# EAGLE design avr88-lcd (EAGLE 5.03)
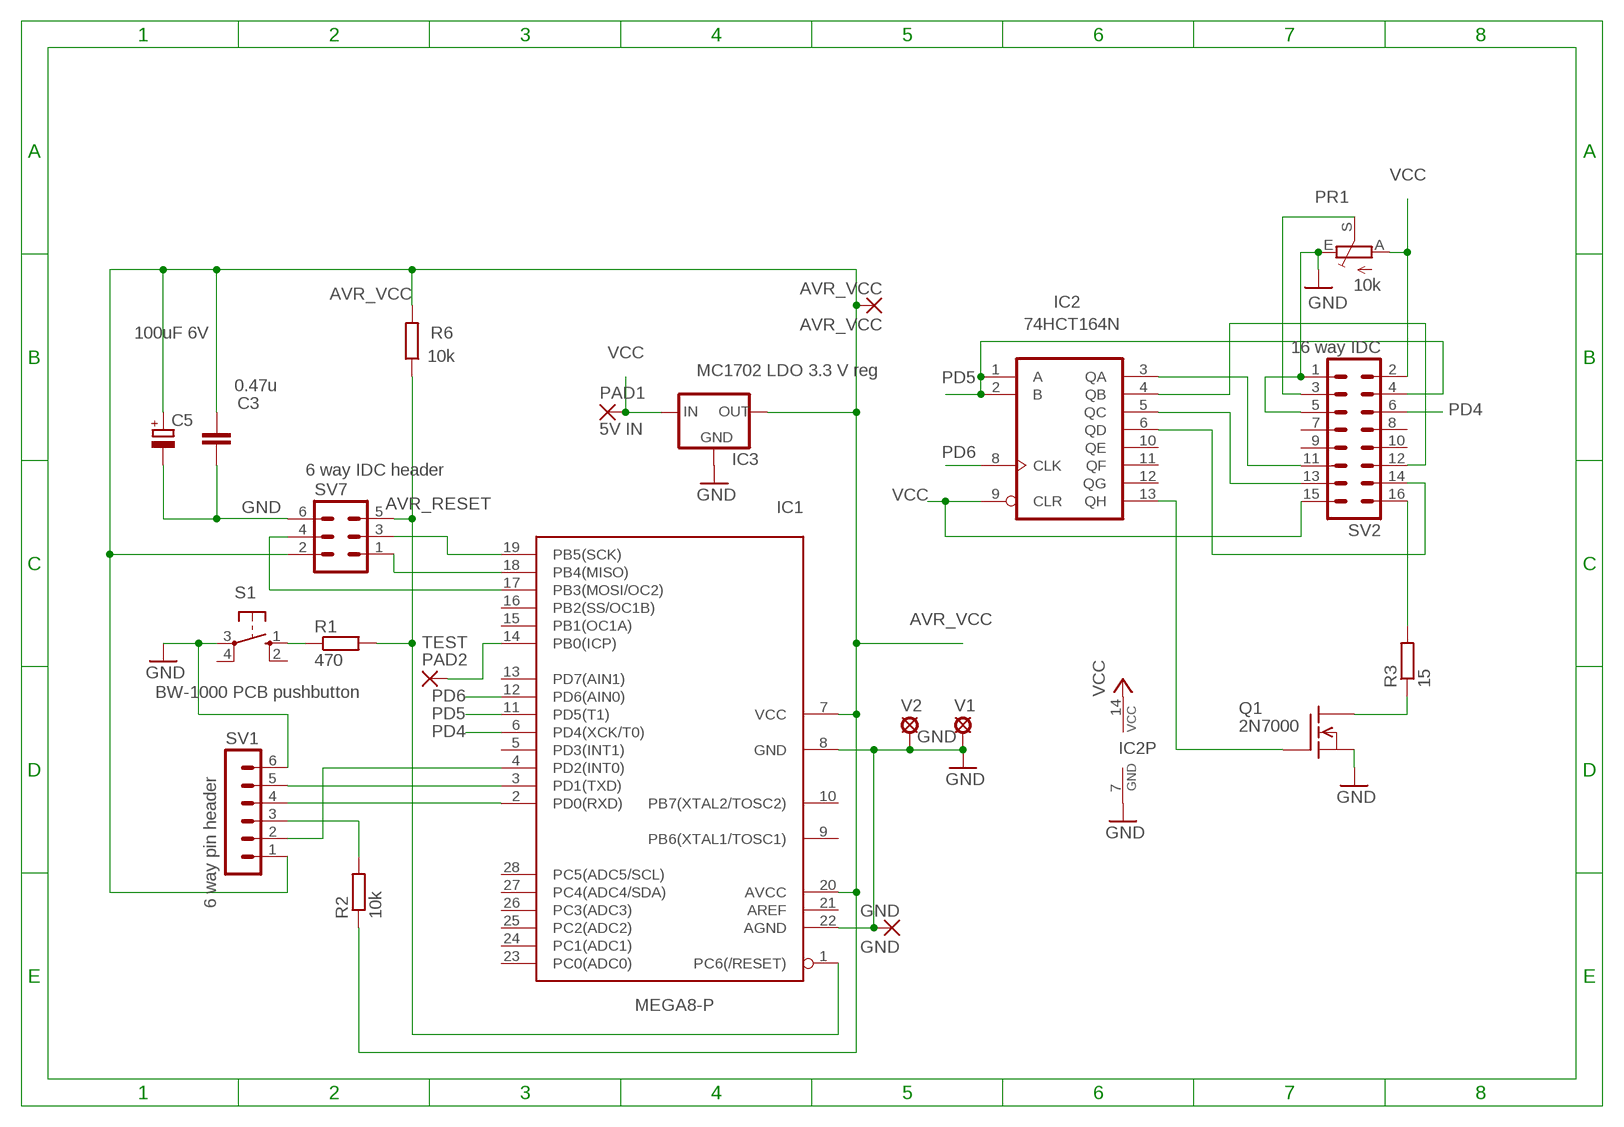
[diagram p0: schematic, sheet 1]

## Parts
AVR_VCC  AVR_VCC  PAD-TERMINAL  [2,54/1,1]
C3  0.47u  C5P  [C050-030-075]
C5  100uF 6V  CPOL1  [E2,5-7---100UF]
GND  GND  PAD-TERMINAL  [2,54/1,1]
IC1  MEGA8-P  [DIL28-3]
IC2  74HCT164N  [DIL14]
IC3  MC1702 LDO 3.3 V reg  XC63FPT  [TO92]
PAD1  5V IN  PAD-TERMINAL  [2,54/1,1]
PAD2  TEST  PAD-TERMINAL  [2,54/1,1]
PR1  10k  VAR_RESISTOR_TRIMS63P  [S63P]
Q1  2N7000  [TO92]
R1  470  R  [0207/10]
R2  10k  R  [0207/10]
R3  15  R  [0207/10]
R6  10k  R  [0207/10]
S1  BW-1000 PCB pushbutton  10-XX  [B3F-10XX]
SV1  6 way pin header  MA06-1  [MA06-1]
SV2  16 way IDC  ML16L  [ML16L]
SV7  6 way IDC header  ML6  [ML6]
V1  HOLE-VIA  [LSP10]
V2  HOLE-VIA  [LSP10]

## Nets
AVR_RESET: IC1.1(PC6(/RESET)) R1.2 R6.1 SV7.5
AVR_VCC: AVR_VCC.1(P) C3.2 C5.+ IC1.7(VCC) IC1.20(AVCC) IC3.3(OUT) R2.1 R6.2 SV1.1 SV7.2
GND [supply]: C3.1 C5.- GND.1(P) IC1.8(GND) IC1.22(AGND) IC2.7(GND) IC3.1(GND) PR1.E Q1.3(S) S1.3(P) SV1.6 SV2.1 SV2.5 SV7.6 V1.MP V2.MP
N$1: Q1.1(D) R3.1
N$2: IC1.19(PB5(SCK)) SV7.3
N$3: IC1.18(PB4(MISO)) SV7.1
N$4: IC1.3(PD1(TXD)) SV1.5
N$5: IC1.2(PD0(RXD)) SV1.4
N$6: IC1.4(PD2(INT0)) SV1.2
N$7: R2.2 SV1.3
N$8: IC1.17(PB3(MOSI/OC2)) SV7.4
N$9: IC2.13(QH) Q1.2(G)
N$10: IC1.14(PB0(ICP)) PAD2.1(P)
N$13: IC2.6(QD) SV2.14
N$14: IC2.5(QC) SV2.13
N$15: IC2.4(QB) SV2.12
N$16: IC2.3(QA) SV2.11
N$17 [supply]: R1.1 S1.1(S)
N$18: PR1.S SV2.3
N$19: R3.2 SV2.16
PD4: IC1.6(PD4(XCK/T0)) SV2.6
PD5: IC1.11(PD5(T1)) IC2.1(A) IC2.2(B) SV2.4
PD6: IC1.12(PD6(AIN0)) IC2.8(CLK)
VCC [supply]: IC2.9(CLR) IC2.14(VCC) IC3.2(IN) PAD1.1(P) PR1.A SV2.2 SV2.15
Unconnected: IC1.5(PD3(INT1)) IC1.9(PB6(XTAL1/TOSC1)) IC1.10(PB7(XTAL2/TOSC2)) IC1.13(PD7(AIN1)) IC1.15(PB1(OC1A)) IC1.16(PB2(SS/OC1B)) IC1.21(AREF) IC1.23(PC0(ADC0)) IC1.24(PC1(ADC1)) IC1.25(PC2(ADC2)) IC1.26(PC3(ADC3)) IC1.27(PC4(ADC4/SDA)) IC1.28(PC5(ADC5/SCL)) IC2.10(QE) IC2.11(QF) IC2.12(QG) S1.2(S1) S1.4(P1) SV2.7 SV2.8 SV2.9 SV2.10

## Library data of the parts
AVR_VCC GND PAD1 PAD2 = ee2parts:PAD-TERMINAL: LARGE THROUGH-HOLE PAD
C3 = ee2parts:C: Capacitor
C5 = ee2parts:CPOL: Electrolytic (polarised) capacitor
IC1 = atmel:MEGA8-P: MICROCONTROLLER 8 Kbytes FLASH, 1 kbytes SRAM, 512 bytes EEPROM, USART, 4-channel 10 bit ADC, 2-channel 8 bit ADC Pin compatible with Atmega48, ATMega88, ATMega168 Source: avr.lbr
IC2 = 74xx-eu:74*164: 8-bit parallel out SHIFT REGISTER
IC3 = v-reg:XC63FP: Positiv Voltage Regulators www.torex.co.jp/english/product/pro02/pdf/0201_xc62fp.pdf
PR1 = ee2parts:VAR_RESISTOR_TRIM: Variable resistor / potentiometer Trimmer potentiometer - Note that slider to end makes variable resistance
Q1 = z-avr-lcd-noPTH:2N7000: N-Channel Enhancement MOSFET 200V; 0,16A; 11Ohm
R1-R3 R6 = ee2parts:R: Resistor
S1 = switch-omron:10-XX: OMRON SWITCH
SV1 = con-lstb:MA06-1: PIN HEADER
SV2 = con-harting-ml:ML16: HARTING
SV7 = con-harting-ml:ML6: HARTING
V1 = ee2parts:HOLE-VIA: FIXED VIA
V2 = z-avr-lcd-noPTH:HOLE-VIA: FIXED VIA

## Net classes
1 supply: width 0.635 mm

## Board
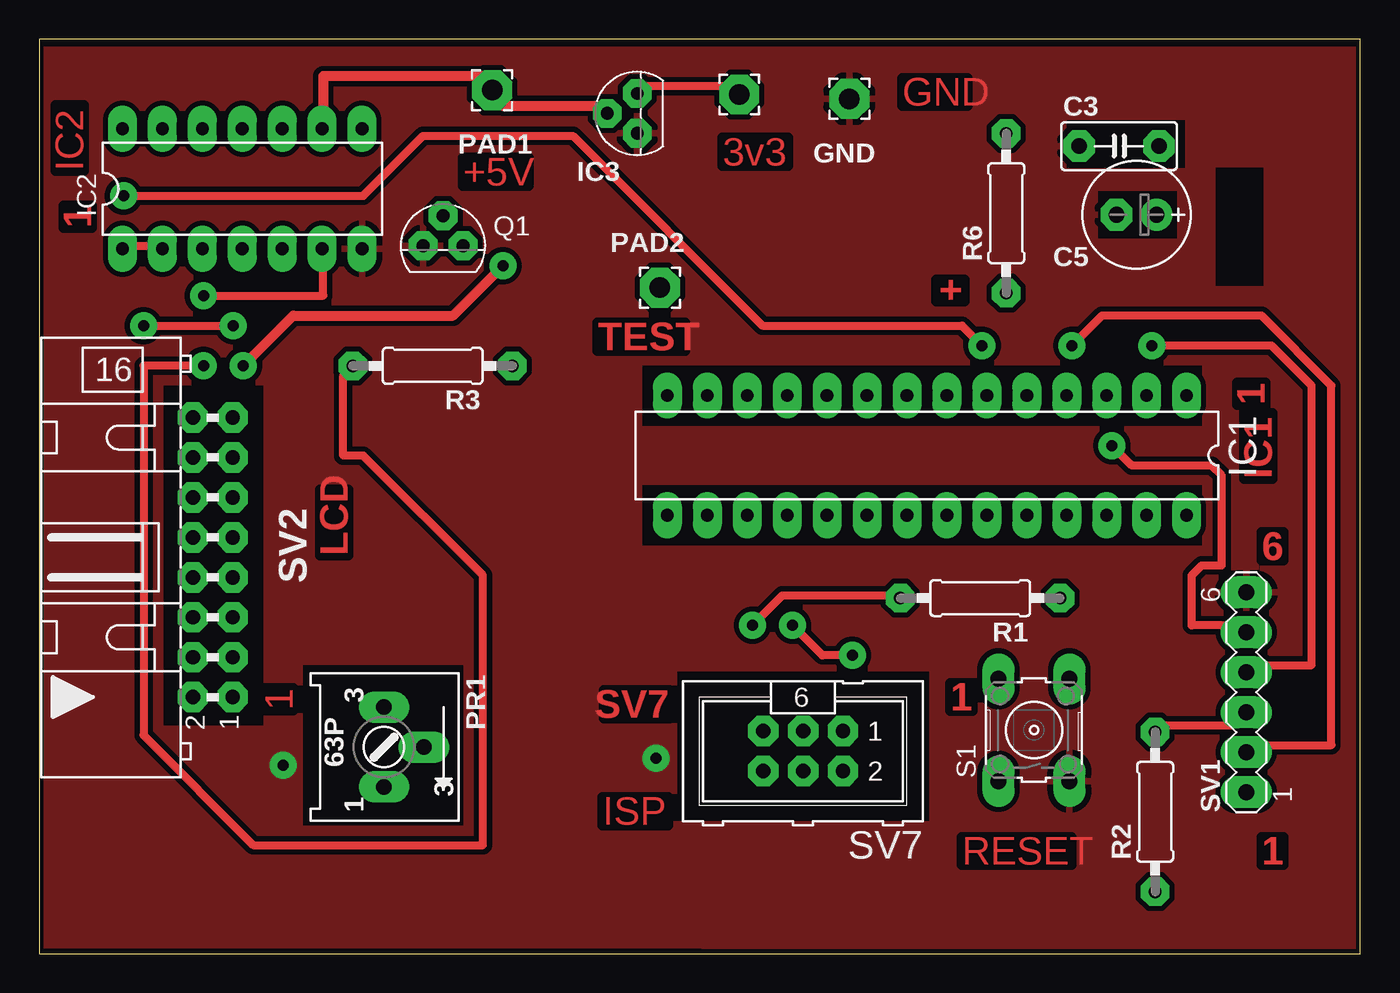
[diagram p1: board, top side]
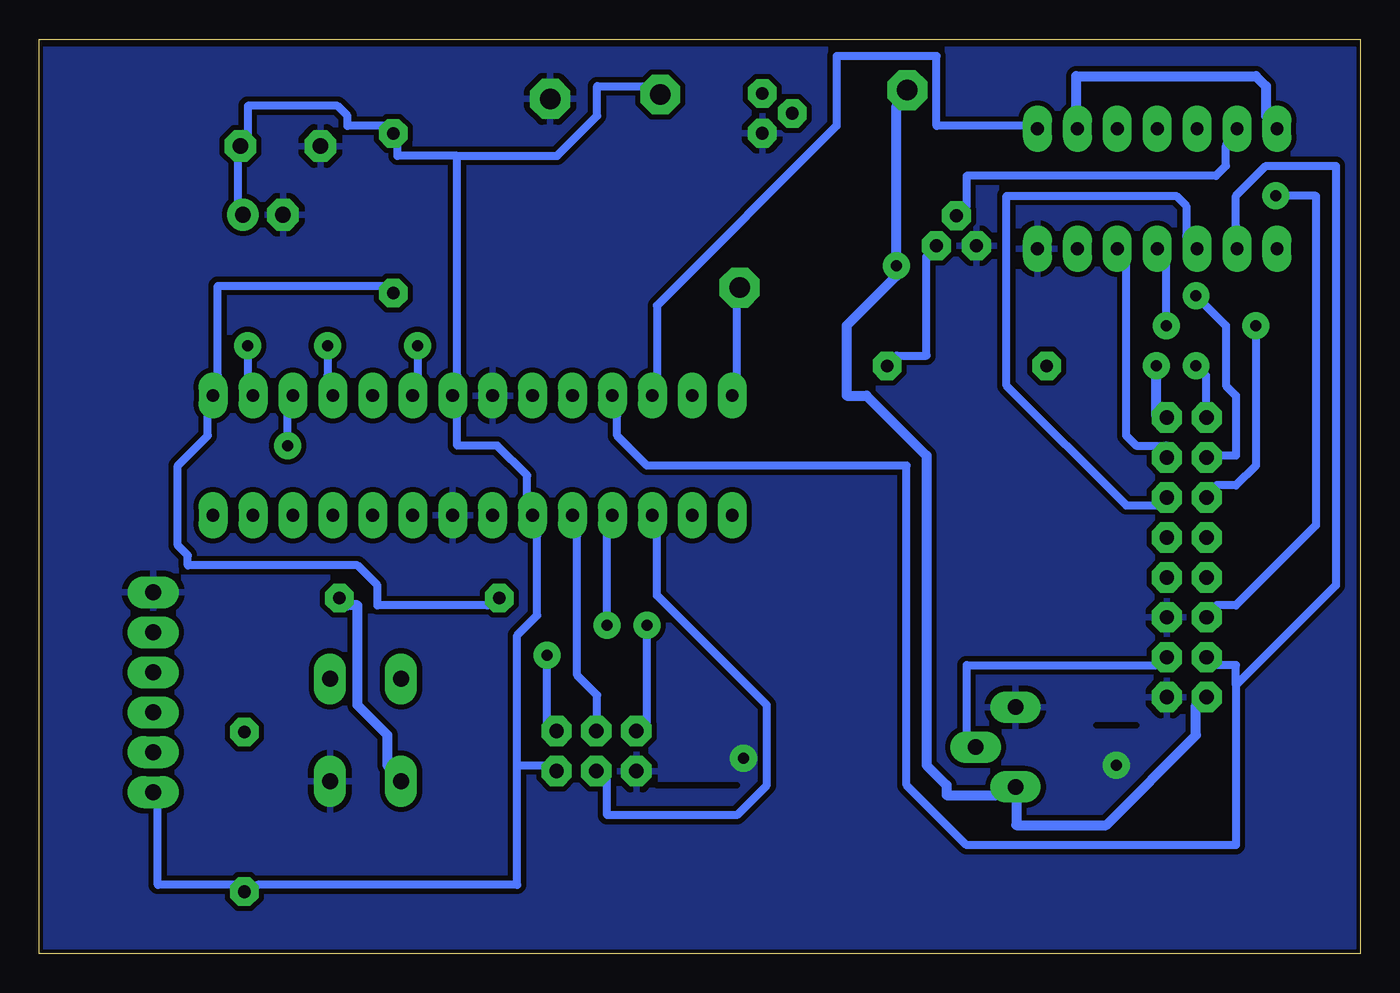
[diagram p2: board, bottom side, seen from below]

Size 84.02 x 58.13 mm. Coordinates in mm from the lower left corner, seen from the top.
Outline: 84.02,0 84.02,58.13 0,58.13 0,0 84.02,0
Copper layers (1*16): Top 0.035mm / dielectric 1.5mm / Bottom 0.035mm
Design rules "zigbit_rules *": minimum track width 20mil, minimum drill 0.7mm, track to track 13mil, track to pad 13mil, pad to pad 13mil, via to via 13mil, smd to smd 0mil, copper to edge 10mil, drill to drill 10mil, minimum pad ring 20mil, minimum via ring 20mil, stop-mask expansion 0mil, vias tented up to drill 0mil, thermal gap 15mil
tRestrict: area 67.3,45.5 to 72.3,48.5; area 65.3,50 to 72.8,53; area 74.8,42.5 to 77.8,50; area 40.6,8.4 to 56.6,17.9; area 7.9,14.5 to 14.3,36.1; area 16.8,8.2 to 27,18.3; area 38.4,33.6 to 73.9,37.4; area 38.4,25.9 to 73.9,29.8
bRestrict: 2 lines
vRestrict: area 0.3,10.7 to 9.2,38.6; area 14.2,14.5 to 19.3,36.1

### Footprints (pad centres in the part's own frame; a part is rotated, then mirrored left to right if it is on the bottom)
2,54/1,1 = drill 1.3 pad 2.54 octagon: 1 0,0
C050-030-075 = drill 1 octagon: 1 -2.54,0; 2 2.54,0
E2,5-7---100UF = drill 1 pad 1.6 round: + -1.27,0 | drill 1 pad 1.6 octagon: - 1.27,0
DIL28-3 = drill 0.813 long: 1 -16.51,-3.81; 2 -13.97,-3.81; 3 -11.43,-3.81; 4 -8.89,-3.81; 5 -6.35,-3.81; 6 -3.81,-3.81; 7 -1.27,-3.81; 8 1.27,-3.81; 9 3.81,-3.81; 10 6.35,-3.81; 11 8.89,-3.81; 12 11.43,-3.81; 13 13.97,-3.81; 14 16.51,-3.81; 15 16.51,3.81; 16 13.97,3.81; 17 11.43,3.81; 18 8.89,3.81; 19 6.35,3.81; 20 3.81,3.81; 21 1.27,3.81; 22 -1.27,3.81; 23 -3.81,3.81; 24 -6.35,3.81; 25 -8.89,3.81; 26 -11.43,3.81; 27 -13.97,3.81; 28 -16.51,3.81
DIL14 = drill 0.813 long: 1 -7.62,-3.81; 2 -5.08,-3.81; 3 -2.54,-3.81; 4 0,-3.81; 5 2.54,-3.81; 6 5.08,-3.81; 7 7.62,-3.81; 8 7.62,3.81; 9 5.08,3.81; 10 2.54,3.81; 11 0,3.81; 12 -2.54,3.81; 13 -5.08,3.81; 14 -7.62,3.81
TO92 = drill 0.813 octagon: 1 -1.27,0; 2 0,1.905; 3 1.27,0
S63P = drill 1 long: A 2.54,0; E -2.54,0; S 0,2.54
TO92' = drill 0.813 octagon: 1 1.27,0; 2 0,1.905; 3 -1.27,0
0207/10 = drill 0.8 octagon: 1 -5.08,0; 2 5.08,0
B3F-10XX = drill 1.016 long: 1 -3.251,2.261; 2 3.251,2.261; 3 -3.251,-2.261; 4 3.251,-2.261
MA06-1 = drill 1.016 long: 1 -6.35,0; 2 -3.81,0; 3 -1.27,0; 4 1.27,0; 5 3.81,0; 6 6.35,0
ML16L = drill 0.914 octagon: 1 -8.89,-1.27; 2 -8.89,1.27; 3 -6.35,-1.27; 4 -6.35,1.27; 5 -3.81,-1.27; 6 -3.81,1.27; 7 -1.27,-1.27; 8 -1.27,1.27; 9 1.27,-1.27; 10 1.27,1.27; 11 3.81,-1.27; 12 3.81,1.27; 13 6.35,-1.27; 14 6.35,1.27; 15 8.89,-1.27; 16 8.89,1.27
ML6 = drill 0.914 octagon: 1 -2.54,-1.27; 2 -2.54,1.27; 3 0,-1.27; 4 0,1.27; 5 2.54,-1.27; 6 2.54,1.27
LSP10 = drill 0.7 pad 1.016 round: MP 0,0

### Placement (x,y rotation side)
AVR_VCC  44.52,54.62 0 top
C3  68.68,51.34 0 top
C5  69.79,46.98 180 top
GND  51.52,54.34 90 top
IC1  56.46,31.67 180 top
IC2  12.91,48.63 0 top
IC3  38.03,53.42 90 top
PAD1  28.81,54.9 180 top
PAD2  39.48,42.34 90 top
PR1  21.92,13.13 270 top
Q1  2N7000  [TO92']  25.68,45 0 top
R1  59.85,22.6 180 top
R2  70.98,9.01 90 top
R3  25.02,37.37 180 top
R6  61.51,47.07 90 top
S1  63.27,14.21 90 top
SV1  76.78,16.61 90 top
SV2  11.03,25.19 90 top
SV7  48.58,12.87 180 top
V1  39.24,12.41 90 top
V2  15.52,11.98 0 top

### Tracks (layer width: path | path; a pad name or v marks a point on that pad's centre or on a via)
AVR_RESET  (via drill 0.7)
  Top 0.508: v45.37,20.87 47.27,22.77 54.26,22.77 R1.2
  Bottom 0.508: v45.37,20.87 45.37,14.52 SV7.5 | R6.1 61.88,42.46 72.67,42.46 72.67,36.74 IC1.1 73.31,34.2 73.31,32.94 75.21,31.03 75.21,25.95 74.58,25.31 74.58,24.68 63.78,24.68 62.51,23.41 62.51,22.14 55.52,22.14 R1.2
AVR_VCC
  Top 0.508: IC3.3 38.38,55.16 43.46,55.16 AVR_VCC.1
  Bottom 0.508: C5.+ 71.4,47.54 71.4,50.71 C3.2 70.77,51.98 70.77,53.89 65.05,53.89 64.42,53.25 64.42,52.62 61.88,52.62 R6.2 61.24,51.35 61.24,50.71 57.43,50.71 | 57.43,50.71 51.08,50.71 48.54,53.25 48.54,55.16 45.37,55.16 AVR_VCC.1 | SV1.1 76.48,9.44 76.48,4.36 71.4,4.36 R2.1 70.13,4.36 53.62,4.36 53.62,11.98 | 53.62,11.98 51.72,11.98 SV7.2 | 53.62,11.98 53.62,20.23 52.35,21.5 52.35,26.58 IC1.20 52.98,29.12 52.98,30.39 54.89,32.3 57.43,32.3 57.43,34.2 IC1.7 57.43,36.74 57.43,50.71
GND
  pour Bottom: 0.35,0.47 0.35,57.47 83.89,57.47 83.89,0.47
  pour Top: 0.35,0.53 0.35,57.47 83.89,57.47 83.89,0.47
N$1
  Bottom 0.508: R3.1 29.49,38.02 27.59,38.02 27.59,44.37 Q1.1
N$2
  Bottom 0.508: IC1.19 49.81,26.58 49.81,17.7 48.54,16.42 48.54,14.52 SV7.3
N$3  (via drill 0.7)
  Top 0.508: v47.91,20.87 49.81,18.96 v51.72,18.96
  Bottom 0.508: v47.91,20.87 47.91,26.58 IC1.18 | v51.72,18.96 51.72,14.52 SV7.1
N$4  (via drill 0.7)
  Top 0.508: v68.22,32.3 69.5,31.03 74.58,31.03 75.21,30.39 75.21,24.68 73.94,24.68 73.31,24.04 73.31,20.87 75.21,20.87 SV1.5
  Bottom 0.508: v68.22,32.3 68.22,34.2 IC1.3
N$5  (via drill 0.7)
  Top 0.508: v70.77,38.65 78.39,38.65 80.92,36.11 80.92,18.33 77.75,18.33 SV1.4
  Bottom 0.508: v70.77,38.65 70.77,36.74 IC1.2
N$6  (via drill 0.7)
  Top 0.508: v65.69,38.65 67.59,40.55 77.75,40.55 82.19,36.11 82.19,13.25 77.75,13.25 SV1.2
  Bottom 0.508: v65.69,38.65 65.69,36.74 IC1.4
N$7
  Top 0.508: R2.2 71.4,14.52 75.84,14.52 SV1.3
N$8
  Bottom 0.508: IC1.17 44.73,26.58 44.73,22.77 37.75,15.79 37.75,10.71 39.65,8.8 47.91,8.8 47.91,11.34 SV7.4
N$9
  Bottom 0.508: IC2.13 8.54,51.35 8.54,50.08 9.17,49.45 25.05,49.45 25.05,47.54 Q1.2
N$10
  Bottom 0.508: IC1.14 39.65,36.74 39.65,41.19 PAD2.1
N$13  (via drill 0.7)
  Top 0.508: v10.44,41.82 18.06,41.82 18.06,43.73 IC2.6
  Bottom 0.508: v10.44,41.82 8.54,39.92 8.54,36.11 7.9,35.48 7.9,31.66 9.17,31.66 SV2.14
N$14
  Bottom 0.508: IC2.5 14.88,43.73 14.88,32.94 14.25,32.3 12.34,32.3 SV2.13
N$15  (via drill 0.7)
  Top 0.508: v6.63,39.92 v12.34,39.92
  Bottom 0.508: v12.34,39.92 12.34,43.73 IC2.4 | v6.63,39.92 6.63,31.03 7.9,29.76 9.17,29.76 SV2.12
N$16
  Bottom 0.508: IC2.3 11.08,45.63 11.08,47.54 11.71,48.17 22.51,48.17 22.51,36.11 14.88,28.49 12.98,28.49 SV2.11
N$17
  Bottom 0.635: R1.1 64.42,22.14 63.78,22.14 63.78,15.79 61.88,13.88 61.88,11.98 S1.1
N$18
  Bottom 0.508: SV2.3 12.98,18.33 25.05,18.33 25.05,13.88 PR1.S
N$19  (via drill 0.7)
  Top 0.508: v10.44,37.38 6.63,37.38 6.63,13.88 13.62,6.9 28.22,6.9 28.22,24.04 20.6,31.66 19.33,31.66 19.33,36.74 R3.2
  Bottom 0.508: v10.44,37.38 9.8,36.74 9.8,34.84 SV2.16
PD4  (via drill 0.7)
  Top 0.508: v59.97,38.65 58.7,39.92 46,39.92 33.94,51.98 24.41,51.98 20.6,48.17 v5.36,48.17
  Bottom 0.508: v59.97,38.65 59.97,36.74 IC1.6 | v5.36,48.17 2.82,48.17 2.82,27.22 7.9,22.14 9.17,22.14 SV2.6
PD5
  Top 0.508: IC2.1 6,45 7.27,45 IC2.2
  Bottom 0.508: 7.9,17.06 7.9,18.33 9.17,18.33 SV2.4 | 7.9,17.06 7.9,6.9 25.05,6.9 28.86,10.71 28.86,31.03 45.37,31.03 47.27,32.94 47.27,34.2 IC1.11 | 7.9,17.06 1.55,23.41 1.55,50.08 6,50.08 7.9,48.17 7.9,46.27 IC2.2
PD6
  Bottom 0.508: IC2.8 21.24,52.62 26.95,52.62 26.95,57.06 33.3,57.06 33.3,52.62 44.73,41.19 44.73,36.74 IC1.12
VCC  (via drill 0.7)
  Top 0.635: IC3.2 35.84,53.89 29.49,53.89 PAD1.1 28.22,55.8 18.06,55.8 18.06,53.89 IC2.9 | v12.98,37.38 16.16,40.55 26.32,40.55 v29.49,43.73
  Bottom 0.635: SV2.2 10.44,15.79 10.44,13.88 16.16,8.17 21.87,8.17 21.87,10.07 PR1.A 23.14,10.07 26.32,10.07 26.32,10.71 27.59,11.98 27.59,31.66 31.4,35.48 32.67,35.48 32.67,39.92 29.49,43.09 v29.49,43.73 29.49,53.89 PAD1.1 | IC2.14 6,53.25 6,55.16 6.63,55.8 18.06,55.8 18.06,53.89 IC2.9 | v12.98,37.38 12.98,34.2 SV2.15

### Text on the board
Top: GND | 3v3 | IC2 | +5V | 1 | + | TEST | 1 | IC1 | LCD | 6 | 1 | SV7 | 1 | ISP | RESET | 1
